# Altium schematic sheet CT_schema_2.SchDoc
size 276 x 169 mm
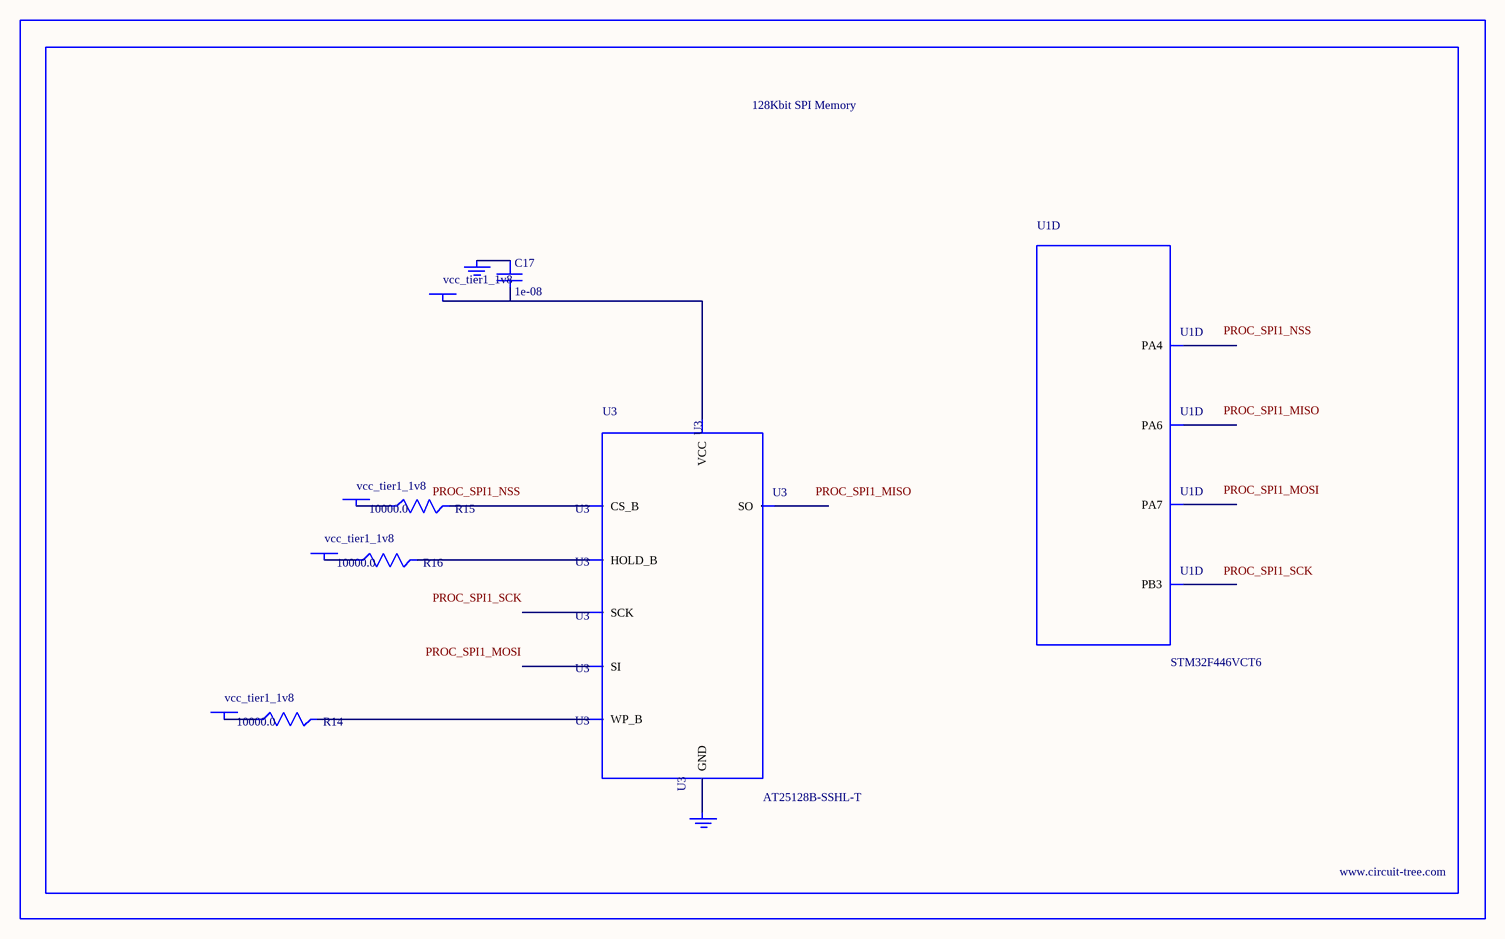
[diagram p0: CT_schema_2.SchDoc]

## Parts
BORDER1  (no value)
C17  1e-08  [C0402]
GND_INSTANCE_1_0  (no value)
GND_INSTANCE_1_1  (no value)
POWER_INSTANCE_1_0  vcc_tier1_1v8
POWER_INSTANCE_1_1  vcc_tier1_1v8
POWER_INSTANCE_1_2  vcc_tier1_1v8
POWER_INSTANCE_1_3  vcc_tier1_1v8
R14  10000.0  [R0603]
R15  10000.0  [R0603]
R16  10000.0  [R0603]
U1  STM32F446VCT6  [LQFP100]  (part D of 9)
U3  AT25128B-SSHL-T  [SOIC-8]

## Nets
NetC17_1: C17.1 GND_INSTANCE_1_0.0(GND)
NetC17_2: C17.2 POWER_INSTANCE_1_3.0(PWR) U3.8(VCC)
NetGND_INSTANCE_1_1_0: GND_INSTANCE_1_1.0(GND) U3.4(GND)
NetPOWER_INSTANCE_1_0_0: POWER_INSTANCE_1_0.0(PWR) R15.1
NetPOWER_INSTANCE_1_1_0: POWER_INSTANCE_1_1.0(PWR) R14.1
NetPOWER_INSTANCE_1_2_0: POWER_INSTANCE_1_2.0(PWR) R16.1
NetR14_2: R14.2 U3.3(WP_B)
NetR15_2: R15.2 U3.1(CS_B)
NetR16_2: R16.2 U3.7(HOLD_B)

Not connected (* = marked no-connect by the designer): U1 29(PA4) 31(PA6) 32(PA7) 89(PB3); U3 2(SO) 5(SI) 6(SCK)

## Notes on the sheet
- Labels drawn without touching a wire or pin: PROC_SPI1_MISO, PROC_SPI1_MOSI, PROC_SPI1_NSS, PROC_SPI1_SCK

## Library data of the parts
BORDER1 = BORDER_PAGE1
C17 = C0402C103K3RAC
GND_INSTANCE_1_0 GND_INSTANCE_1_1 = GND
POWER_INSTANCE_1_0-POWER_INSTANCE_1_3 = PWR
R14-R16 = RC0603JR-0710KL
